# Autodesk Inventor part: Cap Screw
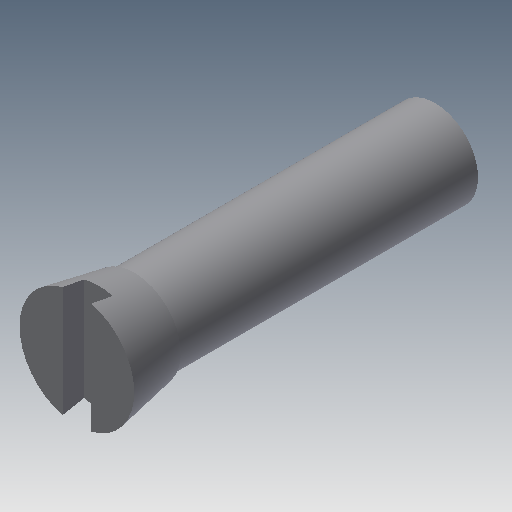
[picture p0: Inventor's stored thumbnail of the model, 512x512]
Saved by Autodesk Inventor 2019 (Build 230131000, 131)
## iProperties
Shininess: 77.0
Length Units: 11269
Angle Units: 11279
Time Units: 11290
Mass Units: 11283
Length Display Precision: 3
Angle Display Precision: 2
Created: 2002-02
Part Number: Cap Screw
Document SubType Name: Modeling
Designer: ***
Density: 1 g/cm^3
Material: Generic
Mass: 0.736586 g
Surface Area: 5.87035 cm^2
Volume: 0.736586 cm^3
Appearance: Default
Density: 0.0
Volumn: 0.0
Area: 0.0
PropertySet Name: Model Information
Control State: 0
Master: False
Checked Out: False
Author: ***
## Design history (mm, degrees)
sketch "Sketch1"
  geometry: L1 (0, 27.83)-(4, 27.83); L2 (4, 27.83)-(3.25, 23.83); L3 (3.25, 23.83)-(0, 23.83); L4 (0, 23.83)-(0, 27.83)
  constraints: 8 end point, 1 horizontal, 1 parallel, 1 perpendicular, 1 point on line
  dimensions: "d2" = 4 distance from line of L1 L2.end; "d5" = 8 diameter of L1.end L4; "d6" = 6.5 diameter of L3.start L4; "d14" = 4 distance of L3.end L1.start
revolve "Revolution1" sketch "Sketch1" stored, may be unused: angle "d7" = 90 deg
sketch "Sketch2"
  geometry: C1 r 3 at (0, 0)
  constraints: 1 centre point
  dimensions: "d8" = 6 diameter of C1
extrude "Extrusion1" join sketch "Sketch2" distance "d9" = 21; taper "d10" = 0 deg
sketch "Sketch3"
  geometry: L1 (-1, 28.967)-(1, 28.967); L2 (1, 28.967)-(1, 26.33); L3 (1, 26.33)-(-1, 26.33); L4 (-1, 26.33)-(-1, 28.967); L5 (-4, 27.83)-(4, 27.83) reference
  constraints: 8 end point, 2 parallel, 1 horizontal, 1 perpendicular
  dimensions: "d11" = 2 distance of L1.start L1.end; "d15" = 1.5 distance between parallel lines of L5 L3
extrude "Extrusion2" cut sketch "Sketch3" extent not by distance; stored distance "d12" = 24; taper "d13" = 0 deg
body "Solid1"
